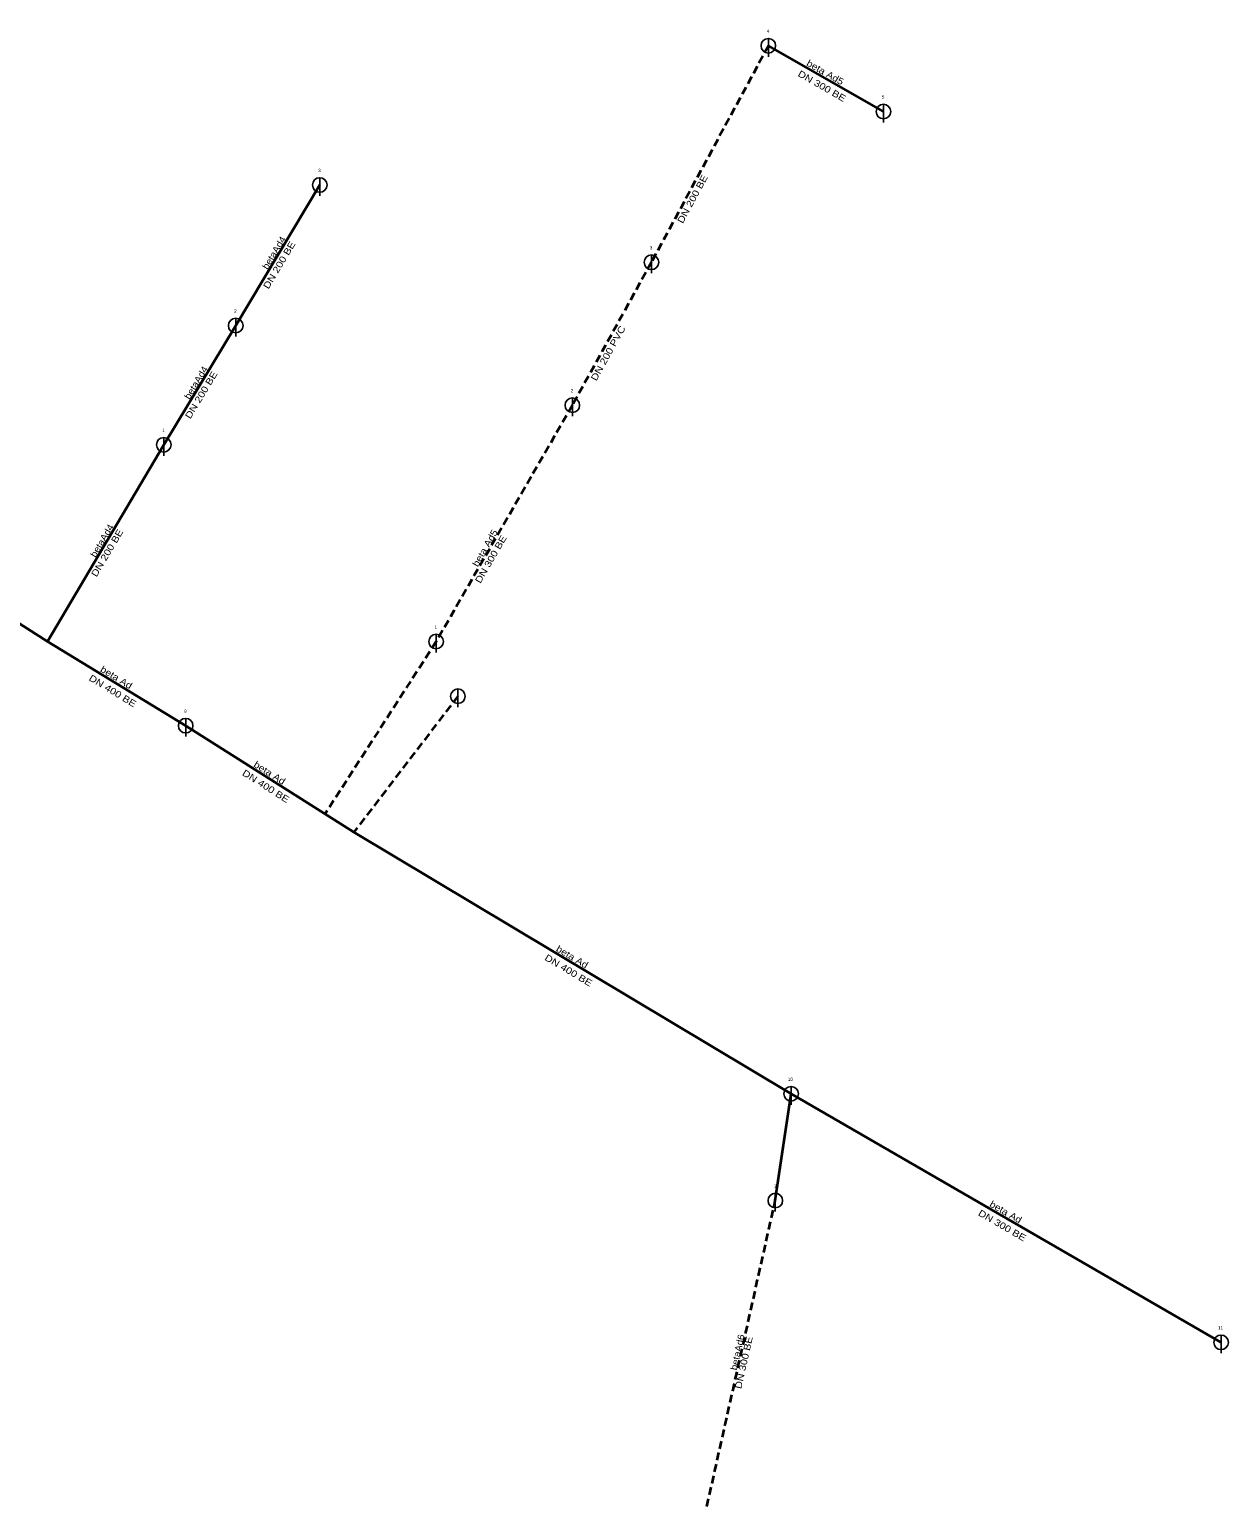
# Model space of a CAD drawing. Extents: x -463285 to -462962, y -1094714 to -1094478.
# Drawn here: x -463126.1 to -462961.9, y -1094714.4 to -1094512 of the extents above; entities that cross this region are included whole.
import ezdxf

# ---------------------------------------------------------------- set-up
doc = ezdxf.new("R2010")
doc.units = 0
doc.header["$LTSCALE"] = 0.36
doc.linetypes.add('MEDIUM_DASHED', pattern=[4.5, 3, -1.5])
for name, color, linetype, lineweight in [('1', 7, 'Continuous', 25), ('13', 7, 'MEDIUM_DASHED', 35), ('18', 7, 'MEDIUM_DASHED', 35), ('63', 7, 'Continuous', 35)]:
    doc.layers.add(name, color=color, linetype=linetype, lineweight=lineweight)
for name, color, linetype in [('14', 7, 'Continuous'), ('2', 7, 'Continuous'), ('21', 7, 'Continuous'), ('31', 7, 'Continuous'), ('34', 7, 'Continuous')]:
    doc.layers.add(name, color=color, linetype=linetype)

msp = doc.modelspace()

# ---------------------------------------------------------------- linework, layer by layer
at = {"layer": '1'}
for p, q in [((-463024.926, -1094513.221), (-463024.926, -1094515.721)), ((-463009.164, -1094522.233), (-463009.164, -1094524.733)), ((-463086.38, -1094532.3), (-463086.38, -1094534.8)), ((-463040.941, -1094542.89), (-463040.941, -1094545.389)), ((-463097.89, -1094551.56), (-463097.89, -1094554.06)), ((-463051.776, -1094562.478), (-463051.776, -1094564.977)), ((-463107.75, -1094567.9), (-463107.75, -1094570.4)), ((-463070.432, -1094594.862), (-463070.432, -1094597.362)), ((-463067.46, -1094602.34), (-463067.46, -1094604.84)), ((-463104.744, -1094606.385), (-463104.744, -1094608.885)), ((-463021.81, -1094656.81), (-463021.81, -1094659.31)), ((-463023.97, -1094671.45), (-463023.97, -1094673.95)), ((-462962.893, -1094690.875), (-462962.893, -1094693.375))]:
    msp.add_line(p, q, dxfattribs=at)
for centre in [(-463024.926, -1094514.221), (-463009.164, -1094523.233), (-463086.38, -1094533.3), (-463040.941, -1094543.89), (-463097.89, -1094552.56), (-463051.776, -1094563.478), (-463107.75, -1094568.9), (-463070.432, -1094595.862), (-463067.46, -1094603.34), (-463104.744, -1094607.385), (-463021.81, -1094657.81), (-463023.97, -1094672.45), (-462962.893, -1094691.875)]:
    msp.add_circle(centre, 1, dxfattribs=at)
at = {"layer": '13'}
msp.add_line((-463033.34, -1094714.36), (-463023.97, -1094672.45), dxfattribs=at)
at = {"layer": '18'}
for p, q in [((-463024.926, -1094514.221), (-463040.941, -1094543.89)), ((-463040.941, -1094543.89), (-463051.776, -1094563.478)), ((-463051.776, -1094563.478), (-463070.432, -1094595.862)), ((-463070.432, -1094595.862), (-463085.655, -1094619.474)), ((-463067.46, -1094603.34), (-463081.702, -1094621.977))]:
    msp.add_line(p, q, dxfattribs=at)
at = {"layer": '63'}
for p, q in [((-463009.164, -1094523.233), (-463024.926, -1094514.221)), ((-463086.38, -1094533.3), (-463097.89, -1094552.56)), ((-463097.89, -1094552.56), (-463107.75, -1094568.9)), ((-463107.75, -1094568.9), (-463123.67, -1094595.84)), ((-463123.67, -1094595.84), (-463150.2, -1094578.91)), ((-463104.744, -1094607.385), (-463123.67, -1094595.84)), ((-463081.702, -1094621.977), (-463104.744, -1094607.385)), ((-463021.81, -1094657.81), (-463081.702, -1094621.977)), ((-463023.97, -1094672.45), (-463021.81, -1094657.81)), ((-462962.893, -1094691.875), (-463021.81, -1094657.81))]:
    msp.add_line(p, q, dxfattribs=at)

# ---------------------------------------------------------------- texts
at = {"layer": '1', "width": 1.2}
for s, rotation, p in [('DN 200 BE', 61.641, (-463036.649, -1094538.655)), ('DN 200 PVC', 61.05, (-463048.498, -1094560.231)), ('DN 300 BE', 60.055, (-463064.373, -1094587.968))]:
    msp.add_text(s, height=0.91, rotation=rotation, dxfattribs=at).set_placement(p)
at = {"layer": '14', "width": 1.1}
msp.add_text('betaAd6', height=0.91, rotation=77.397, dxfattribs=at).set_placement((-463029.245, -1094695.765))
at = {"layer": '2', "width": 1.15}
msp.add_text('beta Ad5', height=0.91, rotation=60.055, dxfattribs=at).set_placement((-463064.74, -1094585.699))
at = {"layer": '21', "width": 1.2}
for s, rotation, p in [('DN 300 BE', 330.241, (-463020.975, -1094518.327)), ('DN 400 BE', 328.617, (-463118.102, -1094601.102)), ('DN 400 BE', 327.655, (-463097.095, -1094614.105)), ('DN 400 BE', 329.108, (-463055.662, -1094639.416)), ('DN 300 BE', 329.964, (-462996.276, -1094674.424))]:
    msp.add_text(s, height=0.91, rotation=rotation, dxfattribs=at).set_placement(p)
at = {"layer": '31', "width": 1.2}
msp.add_text('DN 300 BE', height=0.91, rotation=77.397, dxfattribs=at).set_placement((-463028.641, -1094698.314))
at = {"layer": '34', "width": 1.2}
for rotation, p in [(59.137, (-463093.409, -1094547.637)), (58.892, (-463104.111, -1094565.431)), (59.419, (-463116.965, -1094587.083))]:
    msp.add_text('DN 200 BE', height=0.91, rotation=rotation, dxfattribs=at).set_placement(p)
at = {"layer": '63'}
for s, p in [('4', (-463025.142, -1094512.457)), ('5', (-463009.38, -1094521.469)), ('3', (-463086.596, -1094531.536)), ('3', (-463041.157, -1094542.125)), ('2', (-463098.106, -1094550.796)), ('2', (-463051.992, -1094561.713)), ('1', (-463107.966, -1094567.136)), ('1', (-463070.648, -1094594.098)), ('9', (-463104.96, -1094605.621)), ('10', (-463022.243, -1094656.046)), ('1', (-463024.186, -1094670.686)), ('11', (-462963.326, -1094690.111))]:
    msp.add_text(s, height=0.455, dxfattribs=at).set_placement(p)
for s, rotation, width, p in [('beta Ad5', 330.241, 1.15, (-463019.79, -1094516.874)), ('betaAd4', 59.137, 1.1, (-463093.524, -1094544.972)), ('betaAd4', 58.892, 1.1, (-463104.219, -1094562.766)), ('betaAd4', 59.419, 1.1, (-463117.087, -1094584.419)), ('beta Ad', 328.617, 1.15, (-463116.537, -1094599.908)), ('beta Ad', 327.655, 1.15, (-463095.529, -1094612.938)), ('beta Ad', 329.108, 1.15, (-463054.098, -1094638.209)), ('beta Ad', 329.964, 1.15, (-462994.714, -1094673.194))]:
    msp.add_text(s, height=0.91, rotation=rotation, dxfattribs=dict(at, width=width)).set_placement(p)

doc.saveas('drawing.dxf')
